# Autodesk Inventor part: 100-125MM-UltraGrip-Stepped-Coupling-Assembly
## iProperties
Created: 2012-06
Part Number: 100-125MM-UltraGrip-Stepped-Coupling-Assembly
Document SubType Name: Modeling
Designer: D Cole
Density: 1 g/cm^3
Author: D Cole
